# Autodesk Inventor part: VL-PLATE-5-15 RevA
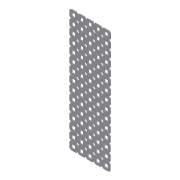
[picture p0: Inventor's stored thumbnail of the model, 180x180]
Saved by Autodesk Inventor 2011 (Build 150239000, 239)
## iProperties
Created: 2008-05
Part Number: VL-PLATE-5-15 RevA
Document SubType Name: Modeling
Density: 1 g/cm^3
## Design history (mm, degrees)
feature "Base1"
sketch "Sketch1" dims "d13" = 25.4, "d20" = 25.4
  geometry: L1 (0, 0)-(8.138, 0) reference; L2 (8.138, 0)-(10.419, 2.281) reference; L3 (10.419, 2.281)-(12.7, 0) reference; L4 (12.7, 0)-(20.838, 0) reference; L5 (20.838, 0)-(23.119, 2.281) reference; L6 (23.119, 2.281)-(25.4, 0) reference; L7 (25.4, 0)-(33.538, 0) reference; L8 (33.538, 0)-(35.819, 2.281) reference; L9 (35.819, 2.281)-(38.1, 0) reference; L10 (38.1, 0)-(46.238, 0) reference; L11 (46.238, 0)-(48.519, 2.281) reference; L12 (48.519, 2.281)-(50.8, 0) reference; L13 (50.8, 0)-(58.938, 0) reference; L14 (58.938, 0)-(61.219, 2.281) reference; L15 (61.219, 2.281)-(61.219, 10.419) reference; L16 (61.219, 10.419)-(58.938, 12.7) reference; L17 (58.938, 12.7)-(61.219, 14.981) reference; L18 (61.219, 14.981)-(61.219, 23.119) reference; L19 (61.219, 23.119)-(58.938, 25.4) reference; L20 (58.938, 25.4)-(61.219, 27.681) reference; L21 (61.219, 27.681)-(61.219, 35.819) reference; L22 (61.219, 35.819)-(58.938, 38.1) reference; L23 (58.938, 38.1)-(61.219, 40.381) reference; L24 (61.219, 40.381)-(61.219, 48.519) reference; L25 (61.219, 48.519)-(58.938, 50.8) reference; L26 (58.938, 50.8)-(61.219, 53.081) reference; L27 (61.219, 53.081)-(61.219, 61.219) reference; L28 (61.219, 61.219)-(58.938, 63.5) reference; L29 (58.938, 63.5)-(61.219, 65.781) reference; L30 (61.219, 65.781)-(61.219, 73.919) reference; L31 (61.219, 73.919)-(58.938, 76.2) reference; L32 (58.938, 76.2)-(61.219, 78.481) reference; L33 (61.219, 78.481)-(61.219, 86.619) reference; L34 (61.219, 86.619)-(58.938, 88.9) reference; L35 (58.938, 88.9)-(61.219, 91.181) reference; L36 (61.219, 91.181)-(61.219, 99.319) reference; L37 (61.219, 99.319)-(58.938, 101.6) reference; L38 (58.938, 101.6)-(61.219, 103.881) reference; L39 (61.219, 103.881)-(61.219, 112.019) reference; L40 (61.219, 112.019)-(58.938, 114.3) reference; L41 (58.938, 114.3)-(61.219, 116.581) reference; L42 (61.219, 116.581)-(61.219, 124.719) reference; L43 (61.219, 124.719)-(58.938, 127) reference; L44 (58.938, 127)-(61.219, 129.281) reference; L45 (61.219, 129.281)-(61.219, 137.419) reference; L46 (61.219, 137.419)-(58.938, 139.7) reference; L47 (58.938, 139.7)-(61.219, 141.981) reference; L48 (61.219, 141.981)-(61.219, 150.119) reference; L49 (61.219, 150.119)-(58.938, 152.4) reference; L50 (58.938, 152.4)-(61.219, 154.681) reference; L51 (61.219, 154.681)-(61.219, 162.819) reference; L52 (61.219, 162.819)-(58.938, 165.1) reference; L53 (58.938, 165.1)-(61.219, 167.381) reference; L54 (61.219, 167.381)-(61.219, 175.519) reference; L55 (61.219, 175.519)-(58.938, 177.8) reference; L56 (58.938, 177.8)-(61.219, 180.081) reference; L57 (61.219, 180.081)-(61.219, 188.219) reference; L58 (61.219, 188.219)-(58.938, 190.5) reference; L59 (58.938, 190.5)-(50.8, 190.5) reference; L60 (50.8, 190.5)-(48.519, 188.219) reference; L61 (48.519, 188.219)-(46.238, 190.5) reference; L62 (46.238, 190.5)-(38.1, 190.5) reference; L63 (38.1, 190.5)-(35.819, 188.219) reference; L64 (35.819, 188.219)-(33.538, 190.5) reference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; C1 r 2.311 at (54.869, 184.15); C2 r 2.311 at (4.069, 184.15); C3 r 2.311 at (54.869, 6.35); C4 r 2.311 at (4.069, 6.35); C5 r 2.311 at (54.869, 171.45); C6 r 2.311 at (54.869, 158.75); C7 r 2.311 at (54.869, 146.05); C8 r 2.311 at (54.869, 133.35); C9 r 2.311 at (54.869, 120.65); C10 r 2.311 at (54.869, 107.95); C11 r 2.311 at (54.869, 95.25); C12 r 2.311 at (54.869, 82.55); C13 r 2.311 at (54.869, 69.85); C14 r 2.311 at (54.869, 57.15); C15 r 2.311 at (54.869, 44.45); C16 r 2.311 at (54.869, 31.75); C17 r 2.311 at (54.869, 19.05); C18 r 2.311 at (4.069, 171.45); C19 r 2.311 at (4.069, 158.75); C20 r 2.311 at (4.069, 146.05); C21 r 2.311 at (4.069, 133.35); C22 r 2.311 at (4.069, 120.65); C23 r 2.311 at (4.069, 107.95); C24 r 2.311 at (4.069, 95.25); C25 r 2.311 at (4.069, 82.55); C26 r 2.311 at (4.069, 69.85); C27 r 2.311 at (4.069, 57.15); C28 r 2.311 at (4.069, 44.45); C29 r 2.311 at (4.069, 31.75); C30 r 2.311 at (4.069, 19.05)
  constraints: 30 centre point, 4 tangent, 3 vertical, 1 horizontal, 58 other
  dimensions: "d2" = 50.8 distance of C1.centre C2.centre; "d5" = 177.8 distance of C1.centre C3.centre; "d10" = 12.7 distance of C1.centre C5.centre; "d17" = 12.7 distance of C2.centre C18.centre
body "Solid1"
